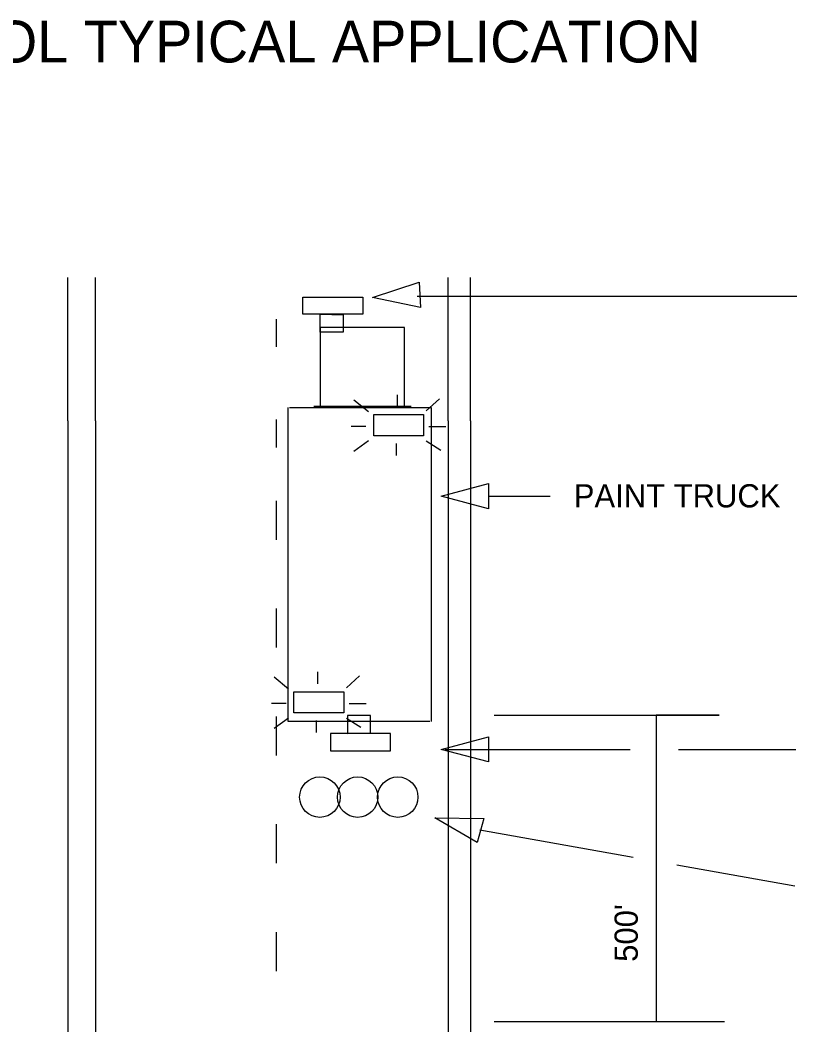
# Model space of a CAD drawing. Extents: x 1531.71 to 1538.58, y 1529.59 to 1539.48.
# Drawn here: x 1534.928 to 1536.939, y 1536.879 to 1539.478 of the extents above; entities that cross this region are included whole.
import ezdxf

# ---------------------------------------------------------------- set-up
doc = ezdxf.new("R2010")
doc.units = 0
for name, color, linetype in [('DETL-DIMS', 7, 'Continuous'), ('DETL-LINE', 7, 'Continuous'), ('DETL-NOTE', 7, 'Continuous'), ('DETL-TITL', 7, 'Continuous'), ('USER-BORD', 7, 'Continuous')]:
    doc.layers.add(name, color=color, linetype=linetype)

# ---------------------------------------------------------------- blocks, each defined once
blk = doc.blocks.new('BAR')
at = {"layer": 'USER-BORD'}
for p, q in [((0.0695, 0.1172), (0.0695, 0.0842)), ((-0.011, 0.0696), (-0.0512, 0.1025)), ((0.15, 0.0732), (0.1866, 0.1062)), ((0.0037, 0.0037), (0.0037, 0.0622)), ((0.0037, 0.0622), (0.1427, 0.0622)), ((0.1427, 0.0622), (0.1427, 0.0037)), ((-0.0183, 0.0293), (-0.0585, 0.0293)), ((0.1573, 0.0293), (0.2049, 0.0293)), ((0.1427, 0.0037), (0.0037, 0.0037)), ((-0.011, -0.011), (-0.0512, -0.0403)), ((0.0658, -0.0183), (0.0658, -0.0513)), ((0.15, -0.011), (0.1902, -0.0366))]:
    blk.add_line(p, q, dxfattribs=at)
blk = doc.blocks.new('SIGN13')
at = {"layer": 'USER-BORD'}
for points in [[(-0.0134, 0.0182), (0.011, 0.0189), (0.011, 0.0371), (-0.0134, 0.0371)], [(-0.0314, 0.0182), (-0.0314, 0), (0.032, 0), (0.032, 0.0182)]]:
    blk.add_lwpolyline(points, close=True, dxfattribs=at)

msp = doc.modelspace()

# ---------------------------------------------------------------- linework, layer by layer
at = {"layer": 'DETL-DIMS'}
for p, q in [((1535.9558, 1538.7637), (1536.9386, 1538.7637)), ((1536.1408, 1538.2465), (1536.2998, 1538.2465)), ((1536.1554, 1537.6802), (1536.7372, 1537.6802)), ((1536.7372, 1537.6802), (1536.5747, 1537.6802)), ((1536.5747, 1537.6802), (1536.5747, 1536.8867)), ((1536.028, 1537.5917), (1536.5067, 1537.5917)), ((1536.6326, 1537.5917), (1536.9361, 1537.5917)), ((1536.1184, 1537.3836), (1536.5146, 1537.3131)), ((1536.6279, 1537.293), (1536.933, 1537.2387)), ((1536.7508, 1536.8867), (1536.1554, 1536.8867))]:
    msp.add_line(p, q, dxfattribs=at)
for points in [[(1535.8404, 1538.7602), (1535.9612, 1538.7999), (1535.965, 1538.735)], [(1536.018, 1538.2465), (1536.1408, 1538.2791), (1536.1408, 1538.214)], [(1536.018, 1537.5917), (1536.1408, 1537.6243), (1536.1408, 1537.5592)], [(1536.0018, 1537.4147), (1536.1289, 1537.4132), (1536.1115, 1537.3504)]]:
    msp.add_lwpolyline(points, close=True, dxfattribs=at)
at = {"layer": 'DETL-LINE'}
for p, q in [((1535.0522, 1538.4412), (1535.0522, 1538.8121)), ((1535.1234, 1538.4412), (1535.1234, 1538.8121)), ((1536.0366, 1538.4412), (1536.0366, 1538.8121)), ((1536.0938, 1538.4412), (1536.0938, 1538.8121)), ((1535.5917, 1538.6325), (1535.5917, 1538.7047)), ((1535.7052, 1538.6825), (1535.7052, 1538.4791)), ((1535.9234, 1538.6825), (1535.7052, 1538.6825)), ((1535.9234, 1538.4791), (1535.9234, 1538.6825)), ((1535.6224, 1537.6639), (1535.6224, 1538.4759)), ((1535.6257, 1538.4759), (1535.9923, 1538.4759)), ((1535.6882, 1538.4791), (1535.9404, 1538.4791)), ((1535.7322, 1538.4759), (1535.9033, 1538.4759)), ((1535.9923, 1538.4759), (1535.9923, 1537.6639)), ((1535.0522, 1538.4412), (1535.0522, 1531.4327)), ((1535.1234, 1538.4412), (1535.1234, 1531.4327)), ((1535.5917, 1538.3726), (1535.5917, 1538.4449)), ((1536.0366, 1538.4412), (1536.0366, 1531.4327)), ((1536.0938, 1538.4412), (1536.0938, 1531.4327)), ((1535.5917, 1538.134), (1535.5917, 1538.2349)), ((1535.5917, 1537.855), (1535.5917, 1537.9559)), ((1535.5917, 1537.5759), (1535.5917, 1537.6769)), ((1535.989, 1537.6639), (1535.6224, 1537.6639)), ((1535.5917, 1537.2969), (1535.5917, 1537.3978)), ((1535.5917, 1537.0179), (1535.5917, 1537.1189))]:
    msp.add_line(p, q, dxfattribs=at)
for centre in [(1535.7042, 1537.4681), (1535.802, 1537.4681), (1535.9058, 1537.4681)]:
    msp.add_circle(centre, 0.0523, dxfattribs=at)

# ---------------------------------------------------------------- block references
for name, p, xscale, yscale in [('SIGN13', (1535.7374, 1538.7617), 2.4478231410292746, -2.4478231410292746), ('BAR', (1535.84, 1538.3996), 0.930070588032, 0.930070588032), ('BAR', (1535.6336, 1537.6829), 0.930070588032, 0.930070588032), ('SIGN13', (1535.8087, 1537.588), 2.4478231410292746, 2.4478231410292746)]:
    msp.add_blockref(name, p, dxfattribs=dict(at, xscale=xscale, yscale=yscale))

# ---------------------------------------------------------------- texts
at = {"layer": 'DETL-NOTE'}
msp.add_text('PAINT TRUCK', height=0.06, dxfattribs=at).set_placement((1536.3612, 1538.2175))
msp.add_text("500'", height=0.06, rotation=90, dxfattribs=at).set_placement((1536.5268, 1537.042))
at = {"layer": 'DETL-TITL'}
msp.add_text('TEMPORARY TRAFFIC CONTROL TYPICAL APPLICATION', height=0.108, dxfattribs=at).set_placement((1532.7424, 1539.3684))

doc.saveas('drawing.dxf')
